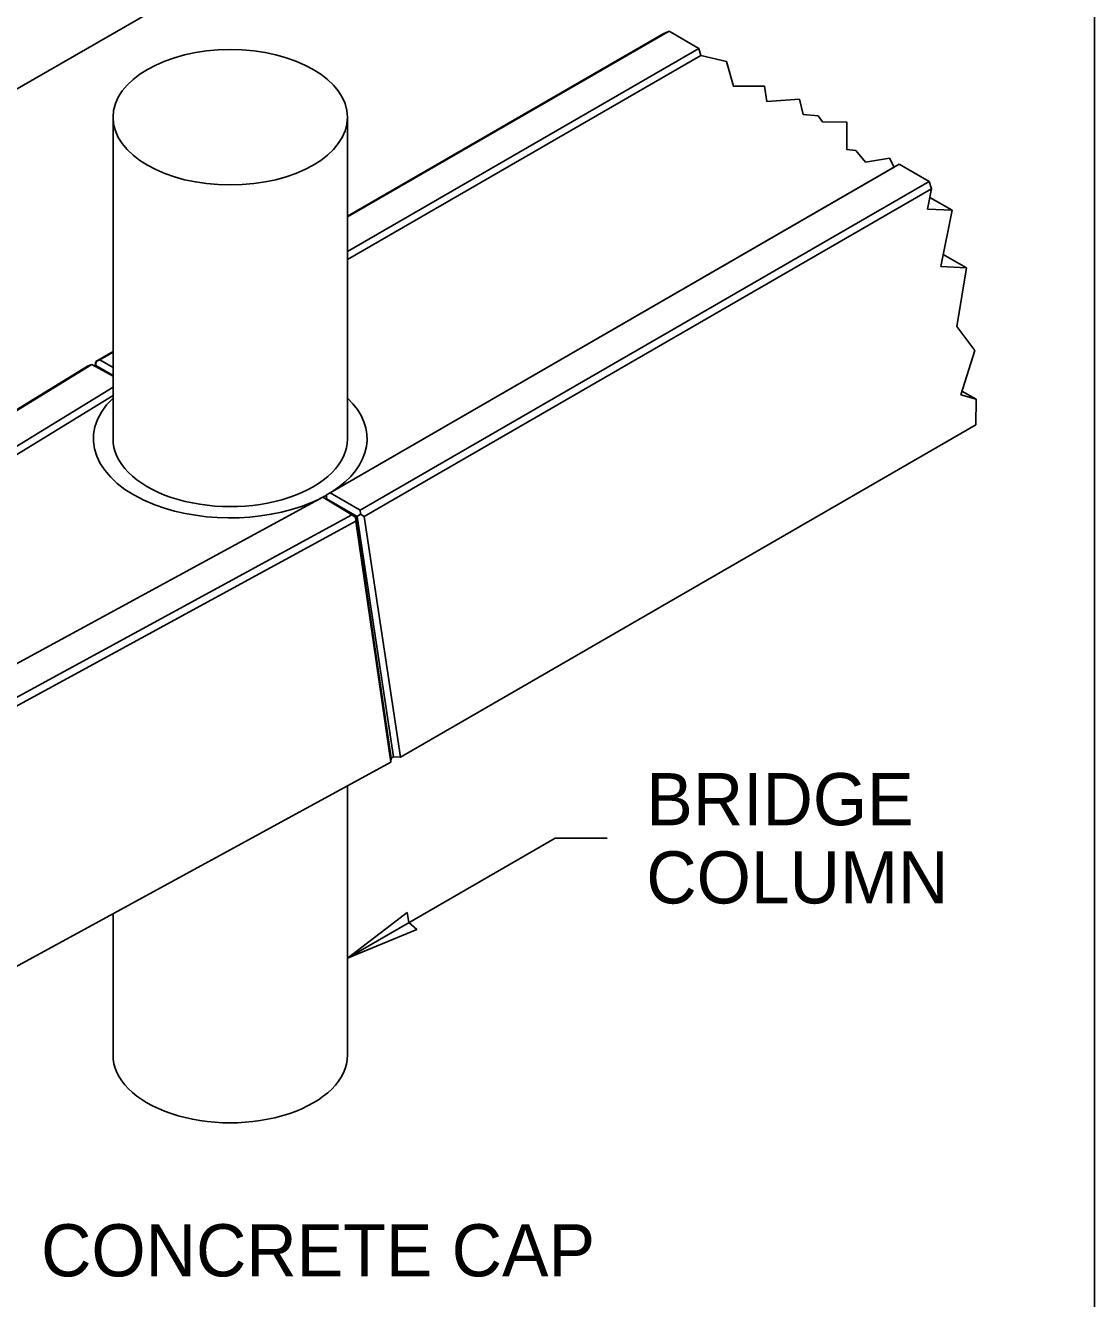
# Model space of a CAD drawing. Extents: x 99862 to 103151, y 100000 to 102076.
# Drawn here: x 102822.9 to 103151, y 100923.4 to 101314 of the extents above; entities that cross this region are included whole.
import ezdxf

# ---------------------------------------------------------------- set-up
doc = ezdxf.new("R2010")
doc.units = 0
for name, color, linetype in [('Level 1', 7, 'Continuous'), ('Level 15', 7, 'Continuous'), ('Level 19', 7, 'Continuous'), ('Level 2', 7, 'Continuous'), ('Level 20', 7, 'Continuous'), ('Level 25', 7, 'Continuous'), ('Level 41', 7, 'Continuous'), ('Level 49', 7, 'Continuous'), ('Level 7', 7, 'Continuous')]:
    doc.layers.add(name, color=color, linetype=linetype)

msp = doc.modelspace()

# ---------------------------------------------------------------- linework, layer by layer
at = {"layer": 'Level 1'}
msp.add_lwpolyline([(99862, 99999.5), (103151, 99999.5), (103151, 102075.5), (99862, 102075.5)], close=True, dxfattribs=at)
at = {"layer": 'Level 15'}
for p, q in [((103034.94, 101418.41), (101857.32, 100738.42)), ((102921.76, 101027.81), (102985.45, 101064.58)), ((102985.45, 101064.58), (103001.45, 101064.58))]:
    msp.add_line(p, q, dxfattribs=at)
msp.add_lwpolyline([(102921.76, 101027.81), (102940.04, 101041.81), (102940.61, 101038.7), (102943.02, 101036.64)], close=True, dxfattribs=at)
at = {"layer": 'Level 19'}
for centre, major_axis, ratio, start_param, end_param in [((102885.79, 101187.13), (42, 0), 0.57735, 2.599042, 4.128226), ((102885.79, 101187.13), (42, 0), 0.57735, 5.543474, 6.825722), ((102885.79, 101187.11), (35.97, 0), 0.577348, 3.136107, 6.283733), ((102885.79, 101187.13), (42, 0), 0.57735, 4.128226, 5.424694)]:
    msp.add_ellipse(centre, major_axis=major_axis, ratio=ratio, start_param=start_param, end_param=end_param, dxfattribs=at)
at = {"layer": 'Level 2'}
for p, q in [((103020.42, 101312.18), (102921.76, 101255.22)), ((103018.64, 101311.4), (102921.76, 101255.47)), ((103020.42, 101312.18), (103018.64, 101311.4)), ((103029.61, 101306.87), (103020.42, 101312.18)), ((103029.61, 101306.87), (102921.76, 101244.6)), ((103029.61, 101306.87), (103030.14, 101304.73)), ((102921.76, 101242.15), (103030.14, 101304.73)), ((103030.14, 101304.73), (103030.14, 101304.73)), ((102849.82, 101285.76), (102849.82, 101187.23)), ((102921.76, 101187.13), (102921.76, 101285.79)), ((103091.07, 101271.39), (102916.42, 101170.56)), ((103100.26, 101266.08), (103091.07, 101271.39)), ((102916.42, 101170.56), (103089.48, 101270.47)), ((103100.26, 101266.08), (102925.62, 101165.25)), ((103101, 101263.85), (102926.88, 101163.32)), ((103099.76, 101257.63), (103101, 101263.85)), ((103101, 101263.85), (103100.26, 101266.08)), ((103100.47, 101261.19), (103107.28, 101257.25)), ((103107.28, 101257.25), (103099.76, 101257.63)), ((103103.85, 101239.99), (103107.28, 101257.25)), ((103111.69, 101239.6), (103103.85, 101239.99)), ((103104.59, 101243.7), (103111.69, 101239.6)), ((103108.76, 101221.61), (103111.69, 101239.6)), ((103114.23, 101214.22), (103108.76, 101221.61)), ((102849.82, 101213.94), (102844.52, 101210.87)), ((102849.82, 101213.68), (102845.77, 101211.35)), ((103109.93, 101200.68), (103114.23, 101214.22)), ((102842.01, 101209.39), (102647.13, 101090.12)), ((102843.3, 101209.89), (102648.42, 101090.62)), ((102842.01, 101209.39), (102843.16, 101209.95)), ((102843.3, 101209.89), (102849.82, 101206.34)), ((102844.53, 101209.62), (102844.19, 101209.41)), ((102844.52, 101210.87), (102844.26, 101209.45)), ((102844.53, 101209.62), (102844.47, 101209.26)), ((102844.62, 101210.81), (102844.53, 101209.62)), ((102849.82, 101206.56), (102844.53, 101209.62)), ((102844.62, 101210.81), (102845.77, 101211.35)), ((102849.82, 101209.01), (102845.77, 101211.35)), ((102849.82, 101202.94), (102657.88, 101085.47)), ((103110.28, 101201.79), (103114.67, 101199.26)), ((103114.67, 101199.26), (103109.93, 101200.68)), ((103114.54, 101191.46), (103114.67, 101199.26)), ((103114.54, 101191.46), (102937.99, 101089.52)), ((102915.36, 101169.95), (102916.42, 101170.56)), ((102915.36, 101168.72), (102915.36, 101169.95)), ((102916.42, 101170.56), (102925.62, 101165.25)), ((102914.17, 101169.28), (102707.59, 101056.77)), ((102923.09, 101163.82), (102914.17, 101169.28)), ((102915.26, 101168.65), (102914.2, 101169.28)), ((102915.26, 101168.65), (102924.36, 101163.09)), ((102915.36, 101168.72), (102924.74, 101163.31)), ((102915.36, 101168.59), (102915.36, 101168.72)), ((102923.09, 101163.82), (102716.51, 101051.31)), ((102924.31, 101161.87), (102717.73, 101049.36)), ((102924.24, 101163.14), (102923.09, 101163.82)), ((102924.31, 101161.87), (102924.24, 101163.14)), ((102935.1, 101087.89), (102924.31, 101161.87)), ((102935.14, 101089.13), (102924.36, 101163.09)), ((102925.73, 101163.99), (102924.74, 101163.31)), ((102924.74, 101163.31), (102935.85, 101089.53)), ((102925.73, 101163.99), (102925.62, 101165.25)), ((102926.88, 101163.32), (102925.73, 101163.99)), ((102926.88, 101163.32), (102937.99, 101089.52)), ((102935.1, 101087.89), (102728.51, 100975.38)), ((102935.14, 101089.13), (102935.1, 101087.89)), ((102935.85, 101089.53), (102935.14, 101089.13)), ((102935.85, 101089.53), (102937.99, 101089.52)), ((102921.76, 101080.62), (102921.76, 100998.07)), ((102849.82, 100997.93), (102849.82, 101041.44))]:
    msp.add_line(p, q, dxfattribs=at)
msp.add_ellipse((102885.79, 101285.78), major_axis=(-35.97, 0), ratio=0.577348, dxfattribs=at)
at = {"layer": 'Level 25'}
msp.add_line((102658.97, 101083.65), (102849.82, 101200.45), dxfattribs=at)
msp.add_lwpolyline([(102915.36, 101168.75), (102915.23, 101168.67)], dxfattribs=at)
at = {"layer": 'Level 41'}
msp.add_lwpolyline([(103030.14, 101304.73), (103038.03, 101302.85), (103040.2, 101295.32), (103049.75, 101295.32), (103050.42, 101290.63), (103060.46, 101291.3), (103061.63, 101286.61), (103066.16, 101286.27), (103067.5, 101284.43), (103075.03, 101284.26), (103075.03, 101275.89), (103077.71, 101275.55), (103080.72, 101272.04), (103088.09, 101273.21), (103089.48, 101270.47)], dxfattribs=at)
msp.add_ellipse((102885.79, 100998.06), major_axis=(35.97, 0), ratio=0.577348, start_param=3.136107, end_param=6.283733, dxfattribs=at)
at = {"layer": 'Level 49'}
msp.add_line((102914.17, 101169.28), (102914.2, 101169.28), dxfattribs=at)
for points in [[(102849.82, 101187.23), (102849.82, 101199.65)], [(102921.76, 101199.65), (102921.76, 101187.13)], [(102915.36, 101169.91), (102915.36, 101169.95), (102916.42, 101170.56), (102916.81, 101170.78)], [(102913.24, 101168.78), (102914.17, 101169.28), (102914.2, 101169.28), (102914.21, 101169.28), (102914.21, 101169.28)]]:
    msp.add_lwpolyline(points, dxfattribs=at)
for centre, major_axis, ratio, start_param, end_param in [((102885.79, 101187.13), (42, 0), 0.57735, 2.599042, 4.128226), ((102885.79, 101187.13), (42, 0), 0.57735, 5.543474, 6.825722), ((102885.79, 101187.11), (35.97, 0), 0.577348, 3.136107, 6.283733), ((102885.79, 101187.13), (42, 0), 0.57735, 5.455728, 5.49363), ((102885.79, 101187.13), (42, 0), 0.57735, 4.128226, 5.424694)]:
    msp.add_ellipse(centre, major_axis=major_axis, ratio=ratio, start_param=start_param, end_param=end_param, dxfattribs=at)
at = {"layer": 'Level 7'}
msp.add_line((102916.81, 101170.78), (102916.42, 101170.56), dxfattribs=at)
msp.add_ellipse((102885.79, 101187.13), major_axis=(42, 0), ratio=0.57735, start_param=5.455728, end_param=5.49363, dxfattribs=at)

# ---------------------------------------------------------------- texts
at = {"layer": 'Level 20'}
for s, p in [('BRIDGE', (103013.45, 101068.59)), ('COLUMN', (103013.45, 101044.59)), ('CONCRETE CAP', (102827.73, 100930.18))]:
    msp.add_text(s, height=16, dxfattribs=at).set_placement(p)

doc.saveas('drawing.dxf')
